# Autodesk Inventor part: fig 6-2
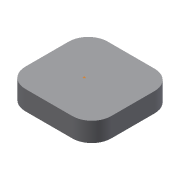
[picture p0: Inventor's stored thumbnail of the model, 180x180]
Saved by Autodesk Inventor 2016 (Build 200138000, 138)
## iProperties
Created: 2004-05
Part Number: fig 6-2
Document SubType Name: Modeling
Designer: CADCIM Technologies
Manufacturer: Standard
Standards Organization: Custom
Density: 1 g/cm^3
Material: Generic
Appearance: Default
Author: CADCIM Technologies
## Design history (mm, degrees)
sketch "Sketch1"
  geometry: L1 (0, 0)-(44.293, 0); L2 (44.293, 0)-(44.293, 42.442); L3 (44.293, 42.442)-(0, 42.442); L4 (0, 42.442)-(0, 0)
  constraints: 8 end point, 2 parallel, 1 horizontal, 1 perpendicular
extrude "Extrusion1" new body sketch "Sketch1" distance "d0" = 10; taper "d1" = 0 deg
fillet "Fillet1" dims "d2" = 10
sketch "Sketch2"
  geometry: 1 further point
sketch "Sketch3"
  geometry: L1 (10, 42.442)-(34.293, 42.442) reference; L2 (0, 10)-(0, 32.442) reference; L3 (34.293, 0)-(10, 0) reference; L4 (44.293, 32.442)-(44.293, 10) reference; A1 r 10 centre (34.293, 32.442) between (44.293, 32.442) and (34.293, 42.442) reference; A2 r 10 centre (10, 32.442) between (10, 42.442) and (0, 32.442) reference; A3 r 10 centre (10, 10) between (0, 10) and (10, 0) reference; A4 r 10 centre (34.293, 10) between (34.293, 0) and (44.293, 10) reference; 1 further point
workpoint "Work Point1"
body "Solid1"
